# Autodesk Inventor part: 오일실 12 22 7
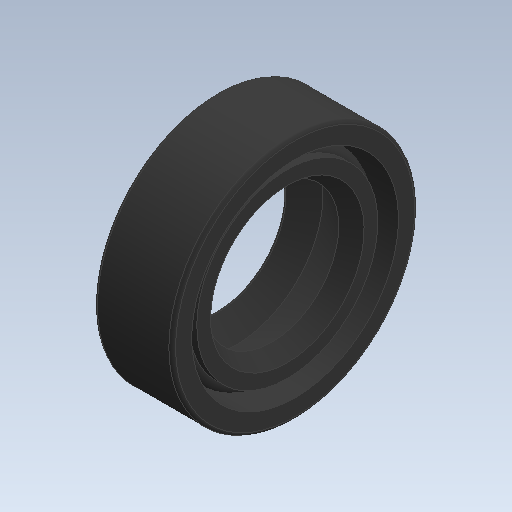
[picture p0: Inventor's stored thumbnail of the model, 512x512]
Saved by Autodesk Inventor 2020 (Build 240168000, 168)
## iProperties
Created: 2024-07
Part Number: 오일실 12 22 7
Material: 고무
Description: 오일-실
Document SubType Name: Modeling
Designer: oem
Density: 0.93 g/cm^3
Appearance: 기본값
Author: jhkim
Sending System: Autodesk Inventor 2025
Preprocessor: ST-DEVELOPER v20
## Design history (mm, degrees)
feature "Solid1"
node "솔리드1"
